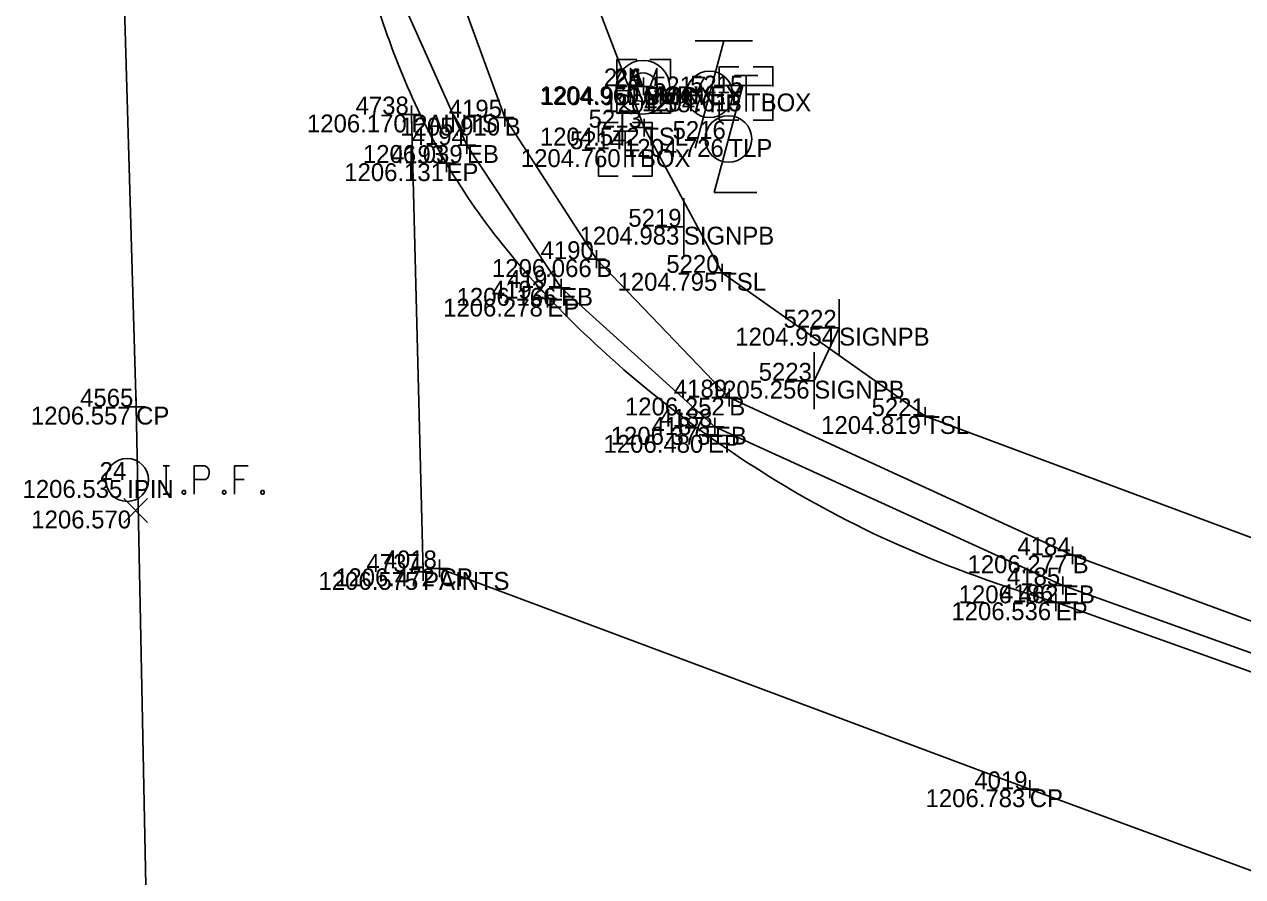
# Model space of a CAD drawing. Extents: x 2044996 to 2050343, y 455232 to 458054.
# Drawn here: x 2047625.4 to 2047693.5, y 456971.3 to 457018.9 of the extents above; entities that cross this region are included whole.
import ezdxf

# ---------------------------------------------------------------- set-up
doc = ezdxf.new("R2010")
doc.units = 0
for name, color, linetype in [('Default', 7, 'Continuous'), ('DT_X_Break_Line', 7, 'Continuous'), ('DT_X_Contour_Minor', 7, 'Continuous'), ('DT_X_Contour_Text', 7, 'Continuous'), ('DT_X_Island', 7, 'Continuous'), ('DT_X_Spot_Elev', 7, 'Continuous'), ('DT_X_TIN_Hull', 7, 'Continuous'), ('DT_X_Triangles', 7, 'Continuous'), ('DT_X_Void', 7, 'Continuous'), ('PM_X_Stop_Line', 7, 'Continuous'), ('PV_X_COP', 7, 'Continuous'), ('PV_X_EOP', 7, 'Continuous'), ('PV_X_Shoulder_Aggregate', 7, 'Continuous'), ('SN_X_Public', 7, 'Continuous'), ('SV_X_Break_Lines', 7, 'Continuous'), ('SV_X_Toe_of_Slope', 7, 'Continuous'), ('UT_X_Electric_Cells', 7, 'Continuous'), ('XS_X_Ground_Line', 7, 'Continuous')]:
    doc.layers.add(name, color=color, linetype=linetype)

msp = doc.modelspace()

# ---------------------------------------------------------------- linework, layer by layer
at = {"layer": 'Default'}
msp.add_lwpolyline([(2047670.954, 457001.971), (2047669.562, 456999.006)], dxfattribs=at)
at = {"layer": 'DT_X_Break_Line'}
for p, q in [((2047660.022, 457015.974), (2047660.022, 457014.974)), ((2047659.522, 457015.474), (2047660.522, 457015.474)), ((2047660.022, 457015.474), (2047660.022, 457015.474))]:
    msp.add_line(p, q, dxfattribs=at)
at = {"layer": 'DT_X_Island'}
for p, q in [((2047665.566, 457015.529), (2047663.959, 457009.529)), ((2047667.166, 457015.529), (2047663.966, 457015.529)), ((2047666.359, 457009.529), (2047663.959, 457009.529))]:
    msp.add_line(p, q, dxfattribs=at)
msp.add_circle((2047664.762, 457012.529), 1.3, dxfattribs=at)
at = {"layer": 'DT_X_Spot_Elev'}
for p, q in [((2047630.958, 456991.077), (2047632.291, 456992.412)), ((2047630.958, 456992.412), (2047632.291, 456991.077))]:
    msp.add_line(p, q, dxfattribs=at)
at = {"layer": 'DT_X_TIN_Hull'}
for p, q in [((2047665.098, 457016.074), (2047666.398, 457016.074)), ((2047665.748, 457014.074), (2047665.748, 457016.074)), ((2047665.748, 457015.074), (2047665.748, 457015.074)), ((2047658.345, 457012.957), (2047659.645, 457012.957)), ((2047658.995, 457010.957), (2047658.995, 457012.957)), ((2047658.995, 457011.957), (2047658.995, 457011.957))]:
    msp.add_line(p, q, dxfattribs=at)
for points in [[(2047665.348, 457016.574), (2047664.248, 457016.574), (2047664.248, 457015.474)], [(2047667.248, 457015.474), (2047667.248, 457016.574), (2047666.148, 457016.574)], [(2047664.248, 457014.674), (2047664.248, 457013.574), (2047665.348, 457013.574)], [(2047666.148, 457013.574), (2047667.248, 457013.574), (2047667.248, 457014.674)], [(2047658.595, 457013.457), (2047657.495, 457013.457), (2047657.495, 457012.357)], [(2047660.495, 457012.357), (2047660.495, 457013.457), (2047659.395, 457013.457)], [(2047657.495, 457011.557), (2047657.495, 457010.457), (2047658.595, 457010.457)], [(2047659.395, 457010.457), (2047660.495, 457010.457), (2047660.495, 457011.557)]]:
    msp.add_lwpolyline(points, dxfattribs=at)
at = {"layer": 'DT_X_Void'}
for p, q in [((2047647.035, 457014.398), (2047647.035, 457013.398)), ((2047652.256, 457014.223), (2047652.256, 457013.223)), ((2047646.535, 457013.898), (2047647.535, 457013.898)), ((2047647.035, 457013.898), (2047647.035, 457013.898)), ((2047651.756, 457013.723), (2047652.756, 457013.723)), ((2047652.256, 457013.723), (2047652.256, 457013.723)), ((2047660.053, 457013.664), (2047660.053, 457012.664)), ((2047659.553, 457013.164), (2047660.553, 457013.164)), ((2047660.053, 457013.164), (2047660.053, 457013.164)), ((2047649.643, 457012.189), (2047650.643, 457012.189)), ((2047650.143, 457012.689), (2047650.143, 457011.689)), ((2047650.143, 457012.189), (2047650.143, 457012.189)), ((2047648.999, 457011.672), (2047648.999, 457010.672)), ((2047648.499, 457011.172), (2047649.499, 457011.172)), ((2047648.999, 457011.172), (2047648.999, 457011.172)), ((2047657.38, 457006.307), (2047657.38, 457005.307)), ((2047656.88, 457005.807), (2047657.88, 457005.807)), ((2047657.38, 457005.807), (2047657.38, 457005.807)), ((2047664.409, 457005.541), (2047664.409, 457004.541)), ((2047655.405, 457004.696), (2047655.405, 457003.696)), ((2047663.909, 457005.041), (2047664.909, 457005.041)), ((2047664.409, 457005.041), (2047664.409, 457005.041)), ((2047654.646, 457004.097), (2047654.646, 457003.097)), ((2047654.905, 457004.196), (2047655.905, 457004.196)), ((2047655.405, 457004.196), (2047655.405, 457004.196)), ((2047654.146, 457003.597), (2047655.146, 457003.597)), ((2047654.646, 457003.597), (2047654.646, 457003.597)), ((2047664.81, 456998.563), (2047664.81, 456997.563)), ((2047631.645, 456998.053), (2047631.645, 456997.053)), ((2047664.31, 456998.063), (2047665.31, 456998.063)), ((2047664.81, 456998.063), (2047664.81, 456998.063)), ((2047631.145, 456997.553), (2047632.145, 456997.553)), ((2047631.645, 456997.553), (2047631.645, 456997.553)), ((2047675.764, 456997.527), (2047675.764, 456996.527)), ((2047664.007, 456996.927), (2047664.007, 456995.927)), ((2047675.264, 456997.027), (2047676.264, 456997.027)), ((2047675.764, 456997.027), (2047675.764, 456997.027)), ((2047663.117, 456995.974), (2047664.117, 456995.974)), ((2047663.507, 456996.427), (2047664.507, 456996.427)), ((2047663.617, 456996.474), (2047663.617, 456995.474)), ((2047663.617, 456995.974), (2047663.617, 456995.974)), ((2047664.007, 456996.427), (2047664.007, 456996.427)), ((2047684.007, 456989.738), (2047684.007, 456988.738)), ((2047648.602, 456989.009), (2047648.602, 456988.009)), ((2047683.507, 456989.238), (2047684.507, 456989.238)), ((2047684.007, 456989.238), (2047684.007, 456989.238)), ((2047647.69, 456988.807), (2047647.69, 456987.807)), ((2047648.102, 456988.509), (2047649.102, 456988.509)), ((2047648.602, 456988.509), (2047648.602, 456988.509)), ((2047647.19, 456988.307), (2047648.19, 456988.307)), ((2047647.69, 456988.307), (2047647.69, 456988.307)), ((2047683.466, 456988.054), (2047683.466, 456987.054)), ((2047682.966, 456987.554), (2047683.966, 456987.554)), ((2047683.069, 456987.11), (2047683.069, 456986.11)), ((2047683.466, 456987.554), (2047683.466, 456987.554)), ((2047682.569, 456986.61), (2047683.569, 456986.61)), ((2047683.069, 456986.61), (2047683.069, 456986.61)), ((2047681.109, 456976.151), (2047682.109, 456976.151)), ((2047681.609, 456976.651), (2047681.609, 456975.651)), ((2047681.609, 456976.151), (2047681.609, 456976.151))]:
    msp.add_line(p, q, dxfattribs=at)
at = {"layer": 'PM_X_Stop_Line'}
msp.add_lwpolyline([(2047647.69, 456988.307), (2047647.035, 457013.898)], dxfattribs=at)
at = {"layer": 'PV_X_COP'}
for points in [[(2047630.621, 457032.63), (2047631.645, 456997.553), (2047632.38, 456961.542), (2047632.831, 456926.921), (2047633.494, 456905.886), (2047634.019, 456875.585), (2047634.745, 456845.706), (2047636.005, 456795.703), (2047636.789, 456753.22), (2047638.144, 456705.836), (2047638.653, 456684.973), (2047639.719, 456638.627)], [(2047648.602, 456988.509), (2047681.609, 456976.151), (2047721.578, 456961.45), (2047764.107, 456945.534)]]:
    msp.add_lwpolyline(points, dxfattribs=at)
at = {"layer": 'PV_X_EOP'}
msp.add_line((2047718.528, 456973.966), (2047683.069, 456986.61), dxfattribs=at)
msp.add_open_spline([(2047683.069, 456986.61), (2047675.937, 456988.736), (2047666.015, 456993.593), (2047654.878, 457002.743), (2047647.768, 457012.145), (2047644.12, 457022.515), (2047642.594, 457029.983), (2047642.214, 457033.05)], degree=3, dxfattribs=at)
at = {"layer": 'PV_X_Shoulder_Aggregate'}
msp.add_lwpolyline([(2047765.405, 456957.602), (2047718.77, 456974.886), (2047683.466, 456987.554), (2047664.007, 456996.427), (2047655.405, 457004.196), (2047650.143, 457012.189), (2047644.762, 457024.201), (2047643.272, 457033.326), (2047642.362, 457078.681), (2047641.183, 457122.013), (2047640.211, 457169.151), (2047639.13, 457212.335), (2047637.968, 457261.485), (2047636.928, 457312.89), (2047635.932, 457367.469)], dxfattribs=at)
at = {"layer": 'SN_X_Public'}
for p, q in [((2047662.266, 457009.22), (2047662.266, 457006.02)), ((2047662.266, 457007.62), (2047660.666, 457007.62)), ((2047670.954, 457003.571), (2047670.954, 457000.371)), ((2047670.954, 457001.971), (2047669.354, 457001.971)), ((2047669.562, 457000.606), (2047669.562, 456997.406)), ((2047669.562, 456999.006), (2047667.962, 456999.006))]:
    msp.add_line(p, q, dxfattribs=at)
at = {"layer": 'SV_X_Break_Lines'}
msp.add_lwpolyline([(2047766.629, 456959.742), (2047718.993, 456976.328), (2047684.007, 456989.238), (2047664.81, 456998.063), (2047657.38, 457005.807), (2047652.256, 457013.723), (2047648.313, 457024.571), (2047646.233, 457034.087), (2047644.074, 457078.243), (2047642.739, 457121.935), (2047641.844, 457169.123), (2047640.705, 457212.333), (2047639.255, 457261.637), (2047638.128, 457312.895), (2047637.801, 457367.098)], dxfattribs=at)
at = {"layer": 'SV_X_Toe_of_Slope'}
msp.add_lwpolyline([(2047656.352, 457022.831), (2047660.053, 457013.164), (2047664.409, 457005.041), (2047675.764, 456997.027), (2047717.961, 456981.302), (2047760.277, 456966.229)], dxfattribs=at)
at = {"layer": 'UT_X_Electric_Cells'}
for p, q in [((2047664.506, 457018.024), (2047662.9, 457012.024)), ((2047666.106, 457018.024), (2047662.906, 457018.024))]:
    msp.add_line(p, q, dxfattribs=at)
msp.add_circle((2047663.703, 457015.024), 1.3, dxfattribs=at)
at = {"layer": 'XS_X_Ground_Line'}
msp.add_line((2047660.022, 457015.474), (2047660.022, 457015.474), dxfattribs=at)
for points in [[(2047658.522, 457015.852), (2047658.522, 457016.975), (2047659.645, 457016.975)], [(2047660.377, 457016.975), (2047661.523, 457016.975), (2047661.523, 457015.852)], [(2047659.282, 457014.474), (2047659.282, 457016.474), (2047660.022, 457014.474), (2047660.762, 457016.474), (2047660.762, 457014.474)], [(2047659.645, 457013.974), (2047658.522, 457013.974), (2047658.522, 457015.095)], [(2047661.523, 457015.095), (2047661.523, 457013.974), (2047660.377, 457013.974)], [(2047633.158, 456994.253), (2047633.511, 456994.253)], [(2047633.334, 456992.653), (2047633.334, 456994.253)], [(2047634.9, 456992.653), (2047634.9, 456994.253), (2047635.429, 456994.253), (2047635.484, 456994.241), (2047635.561, 456994.215), (2047635.594, 456994.19), (2047635.627, 456994.165), (2047635.671, 456994.102), (2047635.704, 456994.039), (2047635.726, 456993.938), (2047635.726, 456993.787), (2047635.715, 456993.737), (2047635.693, 456993.661), (2047635.649, 456993.573), (2047635.605, 456993.535), (2047635.572, 456993.51), (2047635.517, 456993.485), (2047635.429, 456993.472), (2047634.9, 456993.472)], [(2047637.909, 456994.253), (2047637.148, 456994.253), (2047637.148, 456992.653)], [(2047637.148, 456993.472), (2047637.688, 456993.472)], [(2047633.158, 456992.653), (2047633.511, 456992.653)], [(2047634.293, 456992.867), (2047634.348, 456992.867), (2047634.382, 456992.842), (2047634.415, 456992.792), (2047634.415, 456992.729), (2047634.382, 456992.678), (2047634.348, 456992.653), (2047634.293, 456992.653), (2047634.26, 456992.678), (2047634.227, 456992.729), (2047634.227, 456992.792), (2047634.26, 456992.842), (2047634.293, 456992.867)], [(2047636.542, 456992.867), (2047636.597, 456992.867), (2047636.63, 456992.842), (2047636.663, 456992.792), (2047636.663, 456992.729), (2047636.63, 456992.678), (2047636.597, 456992.653), (2047636.542, 456992.653), (2047636.509, 456992.678), (2047636.476, 456992.729), (2047636.476, 456992.792), (2047636.509, 456992.842), (2047636.542, 456992.867)], [(2047638.691, 456992.867), (2047638.746, 456992.867), (2047638.78, 456992.842), (2047638.813, 456992.792), (2047638.813, 456992.729), (2047638.78, 456992.678), (2047638.746, 456992.653), (2047638.691, 456992.653), (2047638.658, 456992.678), (2047638.625, 456992.729), (2047638.625, 456992.792), (2047638.658, 456992.842), (2047638.691, 456992.867)]]:
    msp.add_lwpolyline(points, dxfattribs=at)
for centre, radius in [((2047659.986, 457015.423), 1.5), ((2047659.986, 457015.423), 0.8), ((2047631.144, 456993.453), 1.2)]:
    msp.add_circle(centre, radius, dxfattribs=at)

# ---------------------------------------------------------------- texts
at = {"layer": 'DT_X_Contour_Minor'}
for s, p in [('1204.969', (2047654.204, 457014.474)), ('1204.969', (2047654.204, 457014.474)), ('1204.951', (2047654.268, 457014.423)), ('1204.557', (2047657.823, 457014.024)), ('1204.613', (2047659.922, 457014.074)), ('1206.170', (2047641.198, 457012.898)), ('1205.910', (2047646.418, 457012.723)), ('1204.542', (2047654.22, 457012.164)), ('1206.039', (2047644.325, 457011.189)), ('1204.726', (2047658.921, 457011.529)), ('1204.760', (2047653.157, 457010.957)), ('1206.131', (2047643.282, 457010.172)), ('1204.983', (2047656.44, 457006.62)), ('1206.066', (2047651.54, 457004.807)), ('1204.795', (2047658.562, 457004.041)), ('1206.166', (2047649.564, 457003.196)), ('1206.278', (2047648.81, 457002.597)), ('1204.954', (2047665.146, 457000.971)), ('1205.256', (2047663.721, 456998.006)), ('1206.252', (2047658.977, 456997.063)), ('1206.557', (2047625.765, 456996.553)), ('1204.819', (2047669.947, 456996.027)), ('1206.480', (2047657.779, 456994.974)), ('1206.373', (2047658.181, 456995.427)), ('1206.535', (2047625.296, 456992.453)), ('1206.570', (2047625.787, 456990.744)), ('1206.277', (2047678.128, 456988.238)), ('1206.575', (2047641.843, 456987.307)), ('1206.472', (2047642.769, 456987.509)), ('1206.462', (2047677.633, 456986.554)), ('1206.536', (2047677.228, 456985.61)), ('1206.783', (2047675.783, 456975.151))]:
    msp.add_text(s, height=1, dxfattribs=at).set_placement(p)
at = {"layer": 'DT_X_Contour_Text'}
for s, p in [('CMON', (2047659.986, 457014.423)), ('SURVEY', (2047660.022, 457014.474)), ('MON', (2047660.022, 457014.474)), ('PP', (2047663.703, 457014.024)), ('TBOX', (2047665.748, 457014.074)), ('PAINTS', (2047647.035, 457012.898)), ('B', (2047652.256, 457012.723)), ('TSL', (2047660.053, 457012.164)), ('EB', (2047650.143, 457011.189)), ('TLP', (2047664.762, 457011.529)), ('TBOX', (2047658.995, 457010.957)), ('EP', (2047648.999, 457010.172)), ('SIGNPB', (2047662.266, 457006.62)), ('B', (2047657.38, 457004.807)), ('TSL', (2047664.409, 457004.041)), ('EB', (2047655.405, 457003.196)), ('EP', (2047654.646, 457002.597)), ('SIGNPB', (2047670.954, 457000.971)), ('SIGNPB', (2047669.562, 456998.006)), ('B', (2047664.81, 456997.063)), ('CP', (2047631.645, 456996.553)), ('TSL', (2047675.764, 456996.027)), ('EP', (2047663.617, 456994.974)), ('EB', (2047664.007, 456995.427)), ('IPIN', (2047631.144, 456992.453)), ('B', (2047684.007, 456988.238)), ('PAINTS', (2047647.69, 456987.307)), ('CP', (2047648.602, 456987.509)), ('EB', (2047683.466, 456986.554)), ('EP', (2047683.069, 456985.61)), ('CP', (2047681.609, 456975.151))]:
    msp.add_text(s, height=1, dxfattribs=at).set_placement(p)
at = {"layer": 'DT_X_Triangles'}
for s, p in [('2_1', (2047657.799, 457015.474)), ('2A', (2047658.383, 457015.474)), ('25', (2047658.409, 457015.423)), ('5217', (2047660.541, 457015.024)), ('5215', (2047662.619, 457015.074)), ('4738', (2047643.917, 457013.898)), ('4195', (2047649.126, 457013.723)), ('5213', (2047656.944, 457013.164)), ('5216', (2047661.639, 457012.529)), ('4194', (2047647.053, 457012.189)), ('5214', (2047655.905, 457011.957)), ('4193', (2047645.891, 457011.172)), ('5219', (2047659.166, 457007.62)), ('4190', (2047654.261, 457005.807)), ('5220', (2047661.289, 457005.041)), ('4191', (2047652.406, 457004.196)), ('4192', (2047651.531, 457003.597)), ('5222', (2047667.839, 457001.971)), ('5223', (2047666.453, 456999.006)), ('4565', (2047628.515, 456997.553)), ('4189', (2047661.71, 456998.063)), ('5221', (2047672.765, 456997.027)), ('4188', (2047660.889, 456996.427)), ('4187', (2047660.455, 456995.974)), ('24', (2047629.607, 456993.453)), ('4184', (2047680.917, 456989.238)), ('4737', (2047644.529, 456988.307)), ('4018', (2047645.484, 456988.509)), ('4185', (2047680.337, 456987.554)), ('4186', (2047679.946, 456986.61)), ('4019', (2047678.509, 456976.151))]:
    msp.add_text(s, height=1, dxfattribs=at).set_placement(p)

doc.saveas('drawing.dxf')
